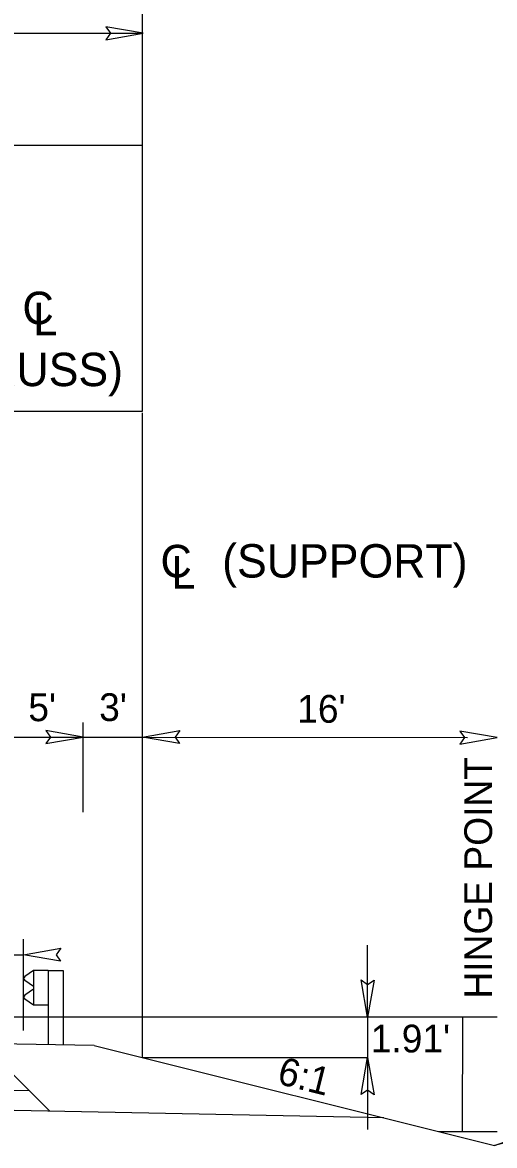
# Model space of a CAD drawing. Extents: x 1725232 to 1728895, y 538685 to 540544.
# Drawn here: x 1725480.9 to 1725504.7, y 539416.1 to 539472.8 of the extents above; entities that cross this region are included whole.
import ezdxf

# ---------------------------------------------------------------- set-up
doc = ezdxf.new("R2010")
doc.units = 0
for name, color, linetype in [('Default', 7, 'Continuous'), ('Prop Dimension Text', 7, 'Continuous'), ('Scratch_Level_0', 7, 'Continuous'), ('Typical Guardrail CELL', 7, 'Continuous'), ('Typical Pavement Slope CELL', 7, 'Continuous'), ('Typical Pavement Slope Information CELL', 7, 'Continuous'), ('Typical Text Centerline CELL', 7, 'Continuous')]:
    doc.layers.add(name, color=color, linetype=linetype)

msp = doc.modelspace()

# ---------------------------------------------------------------- linework, layer by layer
at = {"layer": 'Default'}
for p, q in [((1725486.959, 539453.166), (1725486.959, 539479.171)), ((1725476.83, 539472.231), (1725486.959, 539472.231)), ((1725483.959, 539432.947), (1725483.959, 539437.478)), ((1725478.959, 539436.739), (1725483.959, 539436.739)), ((1725483.959, 539436.739), (1725486.959, 539436.739)), ((1725486.959, 539436.739), (1725503.364, 539436.709)), ((1725480.959, 539421.945), (1725480.959, 539426.537)), ((1725498.318, 539422.604), (1725498.318, 539426.234)), ((1725478.959, 539425.757), (1725480.959, 539425.757)), ((1725504.858, 539422.604), (1725408.092, 539422.604)), ((1725498.318, 539422.604), (1725498.318, 539420.579)), ((1725486.959, 539420.579), (1725498.318, 539420.579)), ((1725498.318, 539420.579), (1725498.318, 539416.949))]:
    msp.add_line(p, q, dxfattribs=at)
for points in [[(1725485.111, 539471.908), (1725486.987, 539472.231), (1725485.101, 539472.565), (1725485.34, 539472.231)], [(1725482.083, 539436.416), (1725483.959, 539436.739), (1725482.072, 539437.072), (1725482.312, 539436.739)], [(1725488.834, 539436.416), (1725486.959, 539436.739), (1725488.845, 539437.072), (1725488.605, 539436.739)], [(1725502.982, 539436.387), (1725504.858, 539436.71), (1725502.972, 539437.043), (1725503.212, 539436.71)], [(1725482.827, 539425.433), (1725480.951, 539425.756), (1725482.837, 539426.089), (1725482.597, 539425.756)], [(1725498.645, 539424.479), (1725498.318, 539422.604), (1725497.989, 539424.491), (1725498.322, 539424.25)], [(1725497.994, 539418.703), (1725498.318, 539420.579), (1725498.651, 539418.693), (1725498.318, 539418.932)]]:
    msp.add_lwpolyline(points, close=True, dxfattribs=at)
at = {"layer": 'Scratch_Level_0'}
for p, q in [((1725476.83, 539466.591), (1725486.959, 539466.591)), ((1725503.111, 539422.604), (1725503.096, 539416.841)), ((1725501.909, 539416.841), (1725504.858, 539416.841))]:
    msp.add_line(p, q, dxfattribs=at)
at = {"layer": 'Typical Guardrail CELL'}
for p, q in [((1725481.457, 539424.959), (1725481.022, 539424.655)), ((1725482.203, 539424.959), (1725481.457, 539424.959)), ((1725481.457, 539424.959), (1725481.457, 539423.218)), ((1725482.203, 539424.959), (1725482.203, 539421.228)), ((1725482.203, 539424.959), (1725482.95, 539424.959)), ((1725482.95, 539424.959), (1725482.95, 539421.228)), ((1725481.457, 539424.159), (1725481.022, 539424.463)), ((1725481.457, 539424.019), (1725481.022, 539423.714)), ((1725481.457, 539423.218), (1725481.022, 539423.523)), ((1725482.203, 539423.218), (1725481.457, 539423.218))]:
    msp.add_line(p, q, dxfattribs=at)
for centre, start, end in [((1725481.089, 539424.559), 125.003, 235.0112), ((1725481.089, 539423.618), 125.0059, 235.0366)]:
    msp.add_arc(centre, 0.117, start, end, dxfattribs=at)
at = {"layer": 'Typical Pavement Slope CELL'}
for p, q in [((1725504.728, 539416.136), (1725523.947, 539422.964)), ((1725484.527, 539421.187), (1725454.94, 539421.667)), ((1725478.959, 539421.187), (1725482.273, 539417.872)), ((1725484.527, 539421.187), (1725504.728, 539416.136)), ((1725481.252, 539418.894), (1725454.94, 539419.42)), ((1725499.133, 539417.535), (1725454.94, 539418.419)), ((1725511.933, 539417.937), (1725504.728, 539416.136))]:
    msp.add_line(p, q, dxfattribs=at)
at = {"layer": 'Typical Text Centerline CELL'}
for p, q in [((1725473.384, 539453.166), (1725486.959, 539453.166)), ((1725486.959, 539420.579), (1725486.959, 539453.088))]:
    msp.add_line(p, q, dxfattribs=at)

# ---------------------------------------------------------------- texts
at = {"layer": 'Default'}
msp.add_text("1.91'", height=1.4011, dxfattribs=at).set_placement((1725498.48, 539420.832))
at = {"layer": 'Prop Dimension Text'}
msp.add_text("3'", height=1.4011, dxfattribs=at).set_placement((1725484.772, 539437.545))
for s, rotation, p in [('HINGE POINT', 90, (1725504.604, 539423.549)), ('6:1', 345.9638, (1725493.698, 539419.27))]:
    msp.add_text(s, height=1.4011, rotation=rotation, dxfattribs=at).set_placement(p)
at = {"layer": 'Typical Pavement Slope Information CELL'}
for s, p in [("5'", (1725481.195, 539437.539)), ("16'", (1725494.769, 539437.461))]:
    msp.add_text(s, height=1.4011, dxfattribs=at).set_placement(p)
at = {"layer": 'Typical Text Centerline CELL'}
for s, height, rotation, p in [('C', 1.64, 0.0443, (1725480.898, 539457.559)), ('L', 1.641, 359.9912, (1725481.444, 539456.999)), ('C', 1.64, 0.0443, (1725487.867, 539444.79)), ('L', 1.641, 359.9912, (1725488.412, 539444.23))]:
    msp.add_text(s, height=height, rotation=rotation, dxfattribs=at).set_placement(p)
for s, p in [('(TRUSS)', (1725476.844, 539454.436)), ('(SUPPORT)', (1725490.978, 539444.782))]:
    msp.add_text(s, height=1.6843, dxfattribs=at).set_placement(p)

doc.saveas('drawing.dxf')
